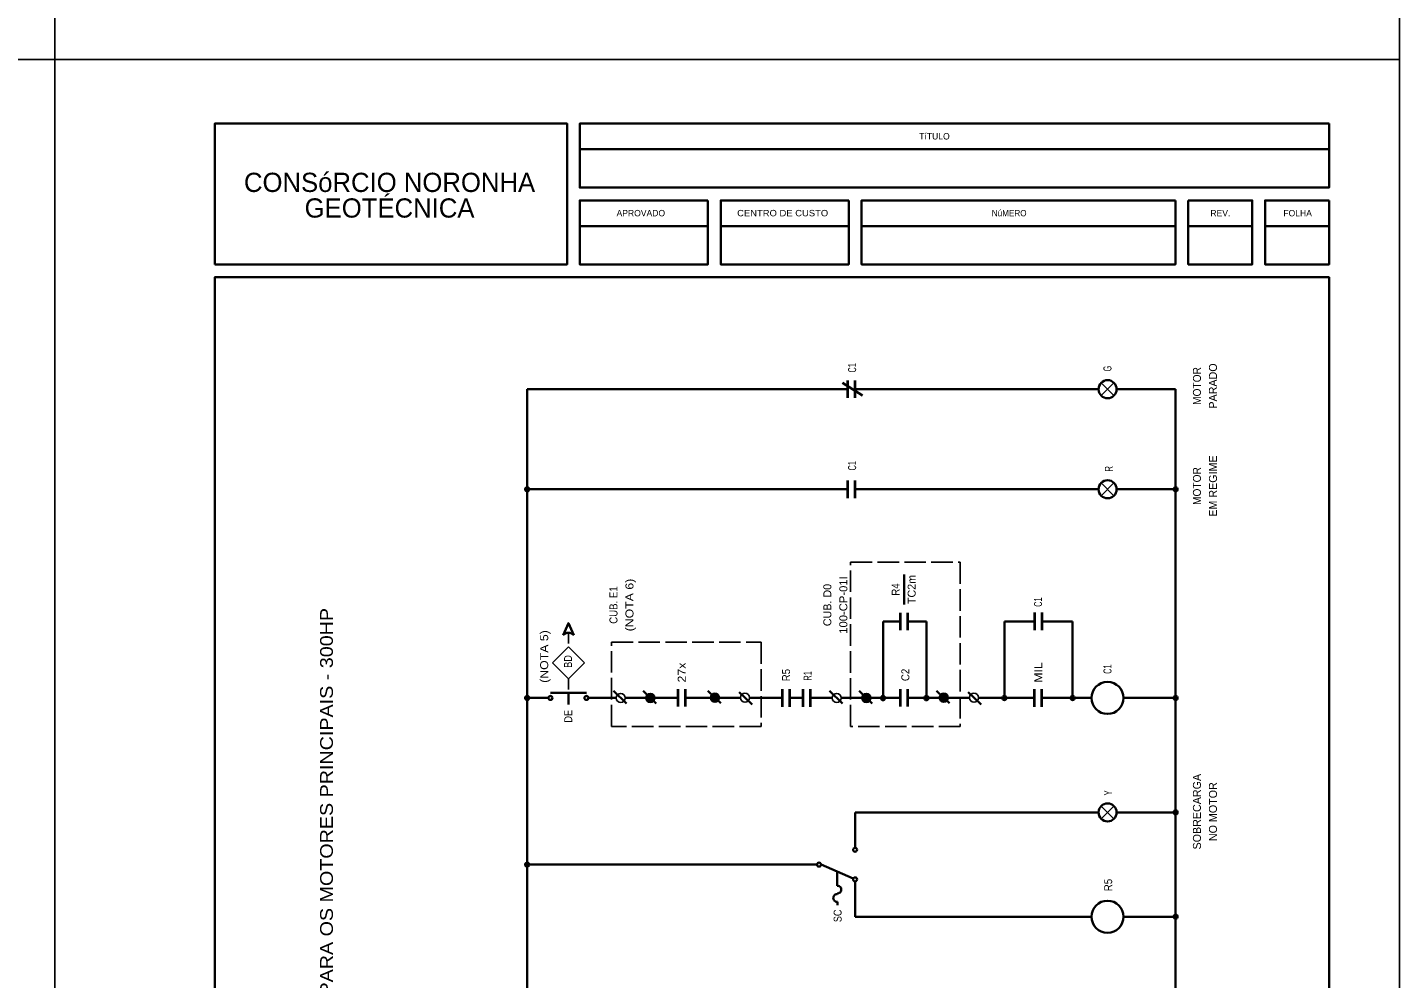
# Model space of a CAD drawing. Extents: x -4160 to -2690, y -474 to 714.
# Drawn here: x -2904 to -2689.8, y -23 to 125.5 of the extents above; entities that cross this region are included whole.
import ezdxf
from ezdxf.enums import TextEntityAlignment as Align

# ---------------------------------------------------------------- set-up
doc = ezdxf.new("R2010")
doc.units = 0
doc.header["$LTSCALE"] = 0.56
doc.linetypes.add('LONG_DASHED', pattern=[7.5, 6, -1.5])
doc.linetypes.add('MEDIUM_DASHED', pattern=[4.5, 3, -1.5])
for name, color, linetype, lineweight in [('1', 7, 'Continuous', 25), ('2', 7, 'Continuous', 25), ('5', 7, 'Continuous', 35)]:
    doc.layers.add(name, color=color, linetype=linetype, lineweight=lineweight)

msp = doc.modelspace()

# ---------------------------------------------------------------- hatches: boundary and pattern name
at = {"layer": '2'}
for points in [[(-2825.9816, 53.7041, 1), (-2825.9816, 53.0594, 1)], [(-2724.7366, 53.7041, 1), (-2724.7366, 53.0594, 1)], [(-2806.7547, 20.1161, 1), (-2806.7547, 21.5209, 1)], [(-2796.6811, 20.1436, 1), (-2796.6811, 21.5484, 1)], [(-2773.0206, 20.1161, 1), (-2773.0206, 21.5209, 1)], [(-2760.9263, 20.1436, 1), (-2760.9263, 21.5484, 1)], [(-2825.9816, 21.1286, 1), (-2825.9816, 20.4839, 1)], [(-2770.416, 21.1011, 1), (-2770.416, 20.4565, 1)], [(-2763.6425, 21.1011, 1), (-2763.6425, 20.4565, 1)], [(-2751.4709, 21.1286, 1), (-2751.4709, 20.484, 1)], [(-2740.822, 21.1286, 1), (-2740.822, 20.484, 1)], [(-2724.7366, 21.1286, 1), (-2724.7366, 20.484, 1)], [(-2724.7366, 3.2537, 1), (-2724.7366, 2.6091, 1)], [(-2825.9816, -4.8867, 1), (-2825.9816, -5.5314, 1)], [(-2724.7359, -13.0273, 1), (-2724.7359, -13.6719, 1)]]:
    msp.add_hatch(color=256, dxfattribs=at).paths.add_polyline_path(points)

# ---------------------------------------------------------------- linework, layer by layer
at = {"layer": '1', "lineweight": 35}
msp.add_lwpolyline([(-2818.7184, 30.5994), (-2819.5398, 32.4995), (-2820.3611, 30.5994)], dxfattribs=at)
at = {"layer": '1', "lineweight": 13}
msp.add_lwpolyline([(-2819.5398, 23.7958), (-2822.0385, 26.2945), (-2819.5398, 28.7933), (-2817.041, 26.2945)], close=True, dxfattribs=at)
at = {"layer": '1', "lineweight": 35}
msp.add_arc((-2819.5398, 29.9309), 1.059, 39.13797, 140.86203, dxfattribs=at)
at = {"layer": '2', "lineweight": 35}
for p, q in [((-2825.9816, -115.2996), (-2825.9816, 69.0067)), ((-2825.9816, 69.0067), (-2775.9185, 69.0067)), ((-2776.7527, 70.0073), (-2773.6011, 68.0184)), ((-2774.7835, 69.0067), (-2736.7749, 69.0067)), ((-2733.9499, 69.0067), (-2724.7366, 69.0067)), ((-2724.7366, 69.0067), (-2724.7366, -115.2996)), ((-2825.9816, 53.3817), (-2775.9185, 53.3817)), ((-2774.7835, 53.3817), (-2736.7749, 53.3817)), ((-2733.9499, 53.3817), (-2724.7366, 53.3817)), ((-2767.1351, 35.42), (-2767.1351, 40.0755)), ((-2770.416, 32.7297), (-2767.7064, 32.7297)), ((-2770.416, 20.7788), (-2770.416, 32.7297)), ((-2766.5714, 32.7572), (-2763.6425, 32.7572)), ((-2763.6425, 20.7788), (-2763.6425, 32.7572)), ((-2751.4709, 32.7572), (-2746.7473, 32.7572)), ((-2751.4709, 20.8063), (-2751.4709, 32.7572)), ((-2745.4929, 32.7572), (-2740.822, 32.7572)), ((-2740.822, 20.8063), (-2740.822, 32.7572)), ((-2816.7273, 21.5992), (-2822.3522, 21.5992)), ((-2819.5398, 21.5992), (-2819.5398, 19.8057)), ((-2812.4933, 21.8933), (-2810.4645, 19.9263)), ((-2807.8741, 21.9055), (-2805.8453, 19.9385)), ((-2797.8006, 21.933), (-2795.7718, 19.966)), ((-2790.8536, 19.7569), (-2792.8824, 21.7239)), ((-2778.7591, 21.8933), (-2776.7303, 19.9263)), ((-2774.14, 21.9055), (-2772.1112, 19.9385)), ((-2762.0457, 21.933), (-2760.0169, 19.966)), ((-2755.0987, 19.7569), (-2757.1275, 21.7239)), ((-2822.6647, 20.8062), (-2825.9816, 20.8062)), ((-2812.0763, 20.8062), (-2816.4148, 20.8062)), ((-2810.6714, 20.8165), (-2802.3977, 20.8165)), ((-2801.2627, 20.844), (-2792.6755, 20.844)), ((-2786.1018, 20.8062), (-2791.2716, 20.8062)), ((-2784.9668, 20.8062), (-2782.8681, 20.8062)), ((-2781.7331, 20.8062), (-2778.3421, 20.8062)), ((-2776.9373, 20.8165), (-2767.7064, 20.8165)), ((-2766.5714, 20.844), (-2756.9206, 20.844)), ((-2755.5157, 20.8063), (-2746.7473, 20.8063)), ((-2745.6123, 20.8063), (-2737.8611, 20.8063)), ((-2732.8644, 20.8063), (-2724.7366, 20.8063)), ((-2774.7835, 2.9314), (-2736.7749, 2.9314)), ((-2774.7835, 2.9314), (-2774.7835, -2.5845)), ((-2733.9499, 2.9314), (-2724.7366, 2.9314)), ((-2825.9816, -5.209), (-2780.7209, -5.209)), ((-2775.07, -7.3963), (-2780.0959, -5.209)), ((-2777.5829, -8.5004), (-2777.5829, -6.3026)), ((-2774.7835, -7.8335), (-2774.7835, -13.3496)), ((-2777.5493, -11.0254), (-2777.5493, -11.5214)), ((-2774.7835, -13.3496), (-2737.8611, -13.3496)), ((-2732.8636, -13.3496), (-2724.7359, -13.3496))]:
    msp.add_line(p, q, dxfattribs=at)
at = {"layer": '2', "lineweight": 40}
for p, q in [((-2775.9185, 67.64), (-2775.9185, 70.3733)), ((-2774.7835, 67.64), (-2774.7835, 70.3733)), ((-2775.9185, 52.015), (-2775.9185, 54.7483)), ((-2774.7835, 52.015), (-2774.7835, 54.7483)), ((-2767.7064, 31.363), (-2767.7064, 34.0963)), ((-2766.5714, 31.363), (-2766.5714, 34.0963)), ((-2746.7473, 34.1238), (-2746.7473, 31.3906)), ((-2745.6123, 34.1238), (-2745.6123, 31.3906)), ((-2802.3977, 19.4498), (-2802.3977, 22.1831)), ((-2801.2627, 19.4498), (-2801.2627, 22.1831)), ((-2786.1018, 19.4396), (-2786.1018, 22.1728)), ((-2784.9668, 19.4396), (-2784.9668, 22.1728)), ((-2782.8681, 19.4396), (-2782.8681, 22.1728)), ((-2781.7331, 19.4396), (-2781.7331, 22.1728)), ((-2767.7064, 19.4498), (-2767.7064, 22.1831)), ((-2766.5714, 19.4498), (-2766.5714, 22.1831)), ((-2746.7473, 19.4397), (-2746.7473, 22.1729)), ((-2745.6123, 19.4397), (-2745.6123, 22.1729))]:
    msp.add_line(p, q, dxfattribs=at)
at = {"layer": '2'}
for p, q in [((-2736.3612, 70.0056), (-2734.3636, 68.008)), ((-2736.3612, 68.008), (-2734.3636, 70.0055)), ((-2736.3612, 54.3806), (-2734.3636, 52.383)), ((-2736.3612, 52.383), (-2734.3636, 54.3805)), ((-2736.3612, 3.9303), (-2734.3636, 1.9327)), ((-2736.3612, 1.9327), (-2734.3636, 3.9302))]:
    msp.add_line(p, q, dxfattribs=at)
at = {"layer": '2', "linetype": 'MEDIUM_DASHED'}
for p, q in [((-2819.5398, 30.9899), (-2819.5398, 28.7933)), ((-2819.5398, 23.7958), (-2819.5398, 21.5992))]:
    msp.add_line(p, q, dxfattribs=at)
at = {"layer": '2', "linetype": 'LONG_DASHED'}
for points in [[(-2775.4823, 16.3478), (-2775.4823, 41.98), (-2758.3756, 41.98), (-2758.3498, 16.3651)], [(-2812.8119, 16.3651), (-2812.8119, 29.5012), (-2789.4661, 29.5012), (-2789.4661, 16.3651)]]:
    msp.add_lwpolyline(points, close=True, dxfattribs=at)
at = {"layer": '2', "lineweight": 35}
for centre, radius in [((-2735.3624, 69.0067), 1.4125), ((-2825.9816, 53.3817), 0.3223), ((-2735.3624, 53.3817), 1.4125), ((-2724.7366, 53.3817), 0.3223), ((-2735.3624, 20.8063), 2.4987), ((-2825.9816, 20.8062), 0.3223), ((-2822.3522, 20.8062), 0.3125), ((-2816.7274, 20.8062), 0.3125), ((-2770.416, 20.7788), 0.3223), ((-2763.6425, 20.7788), 0.3223), ((-2751.4709, 20.8063), 0.3223), ((-2740.822, 20.8063), 0.3223), ((-2724.7366, 20.8063), 0.3223), ((-2735.3624, 2.9314), 1.4125), ((-2724.7366, 2.9314), 0.3223), ((-2774.7835, -2.897), 0.3125), ((-2825.9816, -5.209), 0.3223), ((-2780.4084, -5.2091), 0.3125), ((-2774.7835, -7.5211), 0.3125), ((-2735.3624, -13.3496), 2.4987), ((-2724.7359, -13.3496), 0.3223)]:
    msp.add_circle(centre, radius, dxfattribs=at)
at = {"layer": '2'}
for centre in [(-2811.3738, 20.8062), (-2806.7547, 20.8185), (-2796.6811, 20.846), (-2791.973, 20.844), (-2777.6397, 20.8062), (-2773.0206, 20.8185), (-2760.9263, 20.846), (-2756.2181, 20.844)]:
    msp.add_circle(centre, 0.7024, dxfattribs=at)
at = {"layer": '2', "lineweight": 35}
for centre, start, end in [((-2777.5538, -9.1088), 268.83516, 92.74722), ((-2777.5785, -10.417), 88.83516, 272.74722)]:
    msp.add_arc(centre, 0.6091, start, end, dxfattribs=at)
at = {"layer": '5'}
for p, q in [((-2817.7642, 106.48), (-2700.7642, 106.48)), ((-2817.7642, 94.48), (-2797.7642, 94.48)), ((-2795.7642, 94.48), (-2775.7642, 94.48)), ((-2773.7642, 94.48), (-2724.7642, 94.48)), ((-2722.7642, 94.48), (-2712.7642, 94.48)), ((-2710.7642, 94.48), (-2700.7642, 94.48))]:
    msp.add_line(p, q, dxfattribs=at)
at = {"layer": '5', "lineweight": 25}
for points in [[(-2899.7642, 120.48), (-3109.7642, 120.48), (-3109.7642, 417.48), (-2899.7642, 417.48)], [(-2689.7642, 120.48), (-2899.7642, 120.48), (-2899.7642, 417.48), (-2689.7642, 417.48)], [(-2899.7642, -176.52), (-3109.7642, -176.52), (-3109.7642, 120.48), (-2899.7642, 120.48)], [(-2689.7642, -176.52), (-2899.7642, -176.52), (-2899.7642, 120.48), (-2689.7642, 120.48)]]:
    msp.add_lwpolyline(points, close=True, dxfattribs=at)
at = {"layer": '5'}
for points in [[(-2874.7642, 88.48), (-2874.7642, 110.48), (-2819.7642, 110.48), (-2819.7642, 88.48)], [(-2700.7642, 110.48), (-2817.7642, 110.48), (-2817.7642, 100.48), (-2700.7642, 100.48)], [(-2797.7642, 98.48), (-2817.7642, 98.48), (-2817.7642, 88.48), (-2797.7642, 88.48)], [(-2775.7642, 98.48), (-2795.7642, 98.48), (-2795.7642, 88.48), (-2775.7642, 88.48)], [(-2724.7642, 98.48), (-2773.7642, 98.48), (-2773.7642, 88.48), (-2724.7642, 88.48)], [(-2722.7642, 98.48), (-2712.7642, 98.48), (-2712.7642, 88.48), (-2722.7642, 88.48)], [(-2700.7642, 98.48), (-2710.7642, 98.48), (-2710.7642, 88.48), (-2700.7642, 88.48)], [(-2874.7642, -166.52), (-2874.7642, 86.48), (-2700.7642, 86.48), (-2700.7642, -166.52)]]:
    msp.add_lwpolyline(points, close=True, dxfattribs=at)

# ---------------------------------------------------------------- texts
at = {"layer": '2'}
for s, p in [('PARADO', (-2718.2769, 69.5069)), ('EM REGIME', (-2718.2769, 53.8859)), ('TC2m', (-2765.3264, 37.7371)), ('CUB. D0', (-2778.4936, 35.3106)), ('SOBRECARGA', (-2720.7769, 3.0508)), ('NO MOTOR', (-2718.2769, 3.0507))]:
    msp.add_text(s, height=1.25, rotation=90, dxfattribs=at).set_placement(p, align=Align.CENTER)
for s, width, p in [('C1', 0.55, (-2774.6259, 71.6054)), ('G', 0.6, (-2734.7528, 71.7803)), ('C1', 0.55, (-2774.6259, 56.3152)), ('R', 0.65, (-2734.5295, 56.1569)), ('C1', 0.55, (-2745.5938, 35.0308)), ('(NOTA 5)', 1.15, (-2822.7065, 23.1615)), ('BD', 0.85, (-2818.9815, 25.5134)), ('27x', 1.15, (-2801.2226, 23.221)), ('R5', 0.9, (-2784.9403, 23.4065)), ('R1', 0.55, (-2781.5679, 23.5181)), ('C2', 0.9, (-2766.308, 23.4442)), ('C1', 0.55, (-2734.7502, 24.5663)), ('DE', 0.85, (-2818.951, 16.9583)), ('Y', 0.7, (-2734.6412, 5.595)), ('R5', 0.9, (-2734.6385, -9.3642))]:
    msp.add_text(s, height=1.25, rotation=90, dxfattribs=dict(at, width=width)).set_placement(p)
for s, height, width, p in [('MOTOR', 1.25, 0.95, (-2720.7769, 69.507)), ('MOTOR', 1.25, 0.95, (-2720.7769, 53.886)), ('(NOTA 6)', 1.25, 1.15, (-2809.3882, 35.3106)), ('100-CP-01I', 1.25, 1.05, (-2775.9936, 35.3106)), ('R4', 1.25, 0.9, (-2767.8264, 37.7372)), ('CUB. E1', 1.25, 0.9, (-2811.8882, 35.3106)), ('DIAGRAMA FUNCIONAL TíPICO PARA OS MOTORES PRINCIPAIS - 300HP', 2, 1.15, (-2856.3216, -18.8936)), ('MIL', 1.25, 1.15, (-2745.5666, 24.7833))]:
    msp.add_text(s, height=height, rotation=90, dxfattribs=dict(at, width=width)).set_placement(p, align=Align.CENTER)
at = {"layer": '2', "width": 0.85}
msp.add_text('SC', height=1.25, rotation=90, dxfattribs=at).set_placement((-2776.8853, -12.2243), align=Align.RIGHT)
at = {"layer": '5'}
for s, height, p in [('TíTULO', 1, (-2762.3847, 107.991)), ('CONSóRCIO NORONHA', 3, (-2847.4749, 99.7961)), ('GEOTÉCNICA', 3, (-2847.475, 95.7961)), ('APROVADO', 1, (-2808.2387, 95.9973)), ('REV.', 1, (-2717.7443, 95.9923)), ('FOLHA', 1, (-2705.6809, 95.9923))]:
    msp.add_text(s, height=height, dxfattribs=at).set_placement(p, align=Align.CENTER)
for s, width, p in [('CENTRO DE CUSTO', 1.1, (-2786.0934, 95.9973)), ('NúMERO', 0.95, (-2750.7227, 95.9923))]:
    msp.add_text(s, height=1, dxfattribs=dict(at, width=width)).set_placement(p, align=Align.CENTER)

doc.saveas('drawing.dxf')
